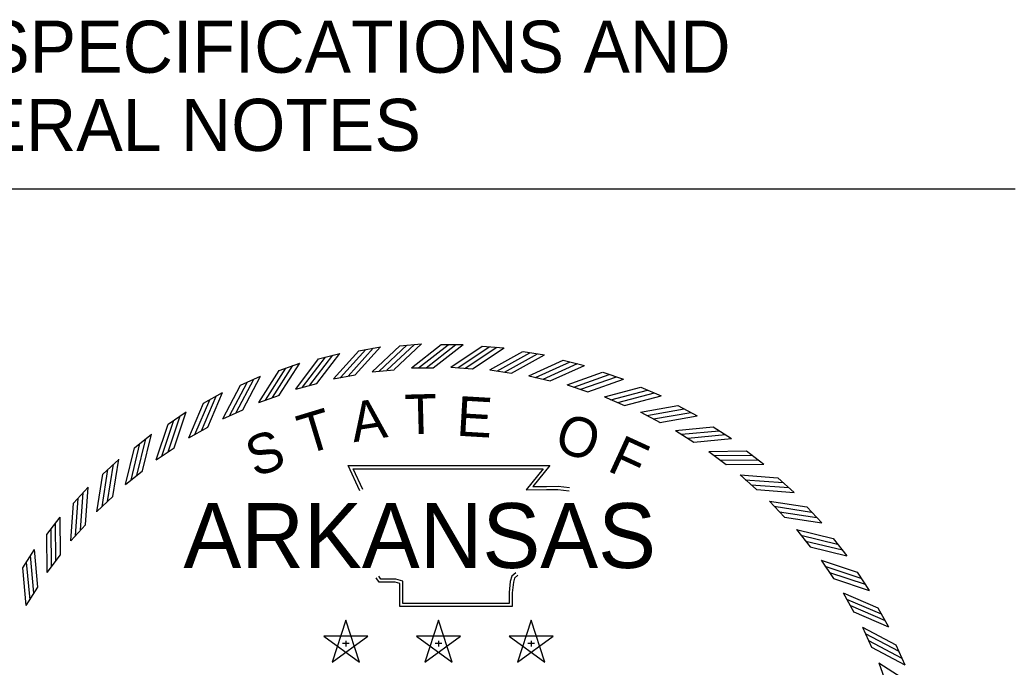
# Model space of a CAD drawing. Extents: x 1955708 to 1956002, y 566396 to 566594.
# Drawn here: x 1955978.59 to 1956002.45, y 566578.57 to 566594.1 of the extents above; entities that cross this region are included whole.
import ezdxf

# ---------------------------------------------------------------- set-up
doc = ezdxf.new("R2010")
doc.units = 0
doc.layers.add('R_Border', color=7, linetype='Continuous')
doc.layers.add('STAMP_PP', color=7, linetype='Continuous')

msp = doc.modelspace()

# ---------------------------------------------------------------- linework, layer by layer
at = {"layer": 'R_Border'}
for p, q in [((1956002.362, 566590.034), (1955939.812, 566590.034)), ((1956002.452, 566590.034), (1955959.352, 566590.034))]:
    msp.add_line(p, q, dxfattribs=at)
at = {"layer": 'STAMP_PP'}
for p, q in [((1955986.717, 566586.161), (1955987.233, 566586.252)), ((1955987.698, 566586.278), (1955988.219, 566586.326)), ((1955988.69, 566586.307), (1955989.214, 566586.307)), ((1955989.671, 566586.268), (1955990.194, 566586.229)), ((1955985.749, 566585.963), (1955986.256, 566586.096)), ((1955990.651, 566586.141), (1955991.169, 566586.059)), ((1955984.801, 566585.686), (1955985.295, 566585.861)), ((1955988.917, 566585.764), (1955989.441, 566585.726)), ((1955991.617, 566585.933), (1955992.126, 566585.809)), ((1955983.879, 566585.332), (1955984.357, 566585.547)), ((1955986.109, 566585.487), (1955986.627, 566585.579)), ((1955987.037, 566585.657), (1955987.56, 566585.705)), ((1955987.975, 566585.75), (1955988.5, 566585.75)), ((1955989.858, 566585.701), (1955990.377, 566585.619)), ((1955990.79, 566585.56), (1955991.3, 566585.436)), ((1955992.562, 566585.646), (1955993.059, 566585.481)), ((1955985.199, 566585.242), (1955985.707, 566585.375)), ((1955991.707, 566585.343), (1955992.206, 566585.177)), ((1955982.989, 566584.902), (1955983.448, 566585.156)), ((1955984.313, 566584.922), (1955984.808, 566585.097)), ((1955992.604, 566585.051), (1955993.086, 566584.845)), ((1955993.48, 566585.283), (1955993.962, 566585.077)), ((1955994.366, 566584.844), (1955994.829, 566584.599)), ((1955982.138, 566584.401), (1955982.574, 566584.692)), ((1955983.455, 566584.53), (1955983.934, 566584.745)), ((1955993.473, 566584.686), (1955993.937, 566584.44)), ((1955995.211, 566584.334), (1955995.653, 566584.052)), ((1955981.331, 566583.831), (1955981.742, 566584.157)), ((1955982.633, 566584.068), (1955983.093, 566584.323)), ((1955994.309, 566584.25), (1955994.751, 566583.967)), ((1955981.852, 566583.54), (1955982.289, 566583.832)), ((1955995.106, 566583.747), (1955995.523, 566583.428)), ((1955996.012, 566583.756), (1955996.429, 566583.438)), ((1955980.574, 566583.197), (1955980.956, 566583.555)), ((1955981.117, 566582.95), (1955981.529, 566583.276)), ((1955995.859, 566583.18), (1955996.248, 566582.828)), ((1955996.763, 566583.114), (1955997.152, 566582.763)), ((1955979.872, 566582.502), (1955980.223, 566582.891)), ((1955980.434, 566582.301), (1955980.817, 566582.66)), ((1955996.562, 566582.552), (1955996.921, 566582.169)), ((1955997.458, 566582.412), (1955997.816, 566582.03)), ((1955979.23, 566581.751), (1955979.548, 566582.168)), ((1955979.806, 566581.597), (1955980.159, 566581.987)), ((1955997.211, 566581.869), (1955997.538, 566581.457)), ((1955998.092, 566581.655), (1955998.418, 566581.244)), ((1955978.652, 566580.95), (1955978.934, 566581.392)), ((1955979.239, 566580.844), (1955979.558, 566581.262)), ((1955997.802, 566581.134), (1955998.093, 566580.697)), ((1955998.662, 566580.848), (1955998.953, 566580.412)), ((1955978.736, 566580.047), (1955979.019, 566580.49)), ((1955998.329, 566580.353), (1955998.584, 566579.893)), ((1955999.164, 566579.997), (1955999.417, 566579.539)), ((1955986.4, 566579.696), (1955986.072, 566578.69)), ((1955986.727, 566578.69), (1955986.401, 566579.697)), ((1955988.623, 566579.696), (1955988.295, 566578.69)), ((1955988.949, 566578.69), (1955988.623, 566579.697)), ((1955990.845, 566579.696), (1955990.518, 566578.69)), ((1955991.172, 566578.69), (1955990.846, 566579.697)), ((1955998.791, 566579.531), (1955999.006, 566579.052)), ((1955986.928, 566579.312), (1955985.871, 566579.313)), ((1955985.871, 566579.312), (1955986.727, 566578.689)), ((1955986.073, 566578.69), (1955986.93, 566579.311)), ((1955986.325, 566579.143), (1955986.482, 566579.143)), ((1955986.401, 566579.199), (1955986.401, 566579.066)), ((1955989.151, 566579.312), (1955988.093, 566579.313)), ((1955988.094, 566579.312), (1955988.949, 566578.689)), ((1955988.296, 566578.69), (1955989.152, 566579.311)), ((1955988.547, 566579.143), (1955988.705, 566579.143)), ((1955988.624, 566579.199), (1955988.624, 566579.066)), ((1955991.374, 566579.312), (1955990.316, 566579.313)), ((1955990.317, 566579.312), (1955991.172, 566578.689)), ((1955990.519, 566578.69), (1955991.375, 566579.311)), ((1955990.77, 566579.143), (1955990.927, 566579.143)), ((1955990.846, 566579.199), (1955990.846, 566579.066)), ((1955999.593, 566579.107), (1955999.808, 566578.63)), ((1955999.183, 566578.674), (1955999.358, 566578.178))]:
    msp.add_line(p, q, dxfattribs=at)
for points in [[(1955986.626, 566585.579), (1955987.233, 566586.252)], [(1955987.036, 566585.657), (1955987.697, 566586.277)], [(1955987.204, 566585.671), (1955987.865, 566586.291)], [(1955987.385, 566585.691), (1955988.046, 566586.312)], [(1955987.559, 566585.706), (1955988.22, 566586.326)], [(1955987.974, 566585.749), (1955988.689, 566586.307)], [(1955988.143, 566585.748), (1955988.858, 566586.305)], [(1955988.325, 566585.752), (1955989.04, 566586.309)], [(1955988.499, 566585.75), (1955989.214, 566586.308)], [(1955988.917, 566585.764), (1955989.671, 566586.267)], [(1955989.085, 566585.75), (1955989.839, 566586.254)], [(1955989.267, 566585.741), (1955990.021, 566586.244)], [(1955985.362, 566585.283), (1955985.912, 566586.004)], [(1955985.537, 566585.333), (1955986.087, 566586.054)], [(1955985.706, 566585.376), (1955986.256, 566586.097)], [(1955986.109, 566585.487), (1955986.716, 566586.16)], [(1955986.275, 566585.515), (1955986.882, 566586.188)], [(1955986.454, 566585.55), (1955987.061, 566586.224)], [(1955989.441, 566585.726), (1955990.195, 566586.23)], [(1955989.857, 566585.701), (1955990.65, 566586.14)], [(1955990.024, 566585.673), (1955990.817, 566586.113)], [(1955990.204, 566585.649), (1955990.997, 566586.088)], [(1955990.376, 566585.62), (1955991.169, 566586.06)], [(1955984.642, 566585.04), (1955985.13, 566585.805)], [(1955984.807, 566585.097), (1955985.295, 566585.861)], [(1955985.199, 566585.241), (1955985.748, 566585.962)], [(1955990.789, 566585.56), (1955991.616, 566585.933)], [(1955990.953, 566585.519), (1955991.779, 566585.891)], [(1955991.131, 566585.48), (1955991.957, 566585.852)], [(1955991.3, 566585.437), (1955992.126, 566585.809)], [(1955983.934, 566584.745), (1955984.357, 566585.547)], [(1955984.312, 566584.921), (1955984.8, 566585.685)], [(1955984.472, 566584.976), (1955984.96, 566585.74)], [(1955991.707, 566585.343), (1955992.561, 566585.646)], [(1955991.866, 566585.288), (1955992.721, 566585.591)], [(1955992.04, 566585.235), (1955992.895, 566585.538)], [(1955983.455, 566584.529), (1955983.878, 566585.331)], [(1955983.609, 566584.597), (1955984.033, 566585.399)], [(1955983.774, 566584.675), (1955984.197, 566585.477)], [(1955992.205, 566585.178), (1955993.06, 566585.481)], [(1955982.939, 566584.239), (1955983.294, 566585.073)], [(1955983.092, 566584.323), (1955983.448, 566585.157)], [(1955992.603, 566585.051), (1955993.479, 566585.283)], [(1955992.757, 566584.983), (1955993.634, 566585.215)], [(1955992.926, 566584.915), (1955993.803, 566585.147)], [(1955993.086, 566584.845), (1955993.963, 566585.077)], [(1955982.633, 566584.068), (1955982.989, 566584.902)], [(1955982.781, 566584.148), (1955983.137, 566584.982)], [(1955993.472, 566584.686), (1955994.365, 566584.844)], [(1955982.142, 566583.736), (1955982.428, 566584.597)], [(1955982.289, 566583.832), (1955982.574, 566584.692)], [(1955993.62, 566584.606), (1955994.513, 566584.764)], [(1955993.783, 566584.524), (1955994.676, 566584.682)], [(1955993.936, 566584.441), (1955994.829, 566584.599)], [(1955981.852, 566583.54), (1955982.138, 566584.4)], [(1955981.993, 566583.632), (1955982.279, 566584.492)], [(1955994.308, 566584.25), (1955995.211, 566584.334)], [(1955981.528, 566583.276), (1955981.742, 566584.157)], [(1955994.449, 566584.158), (1955995.352, 566584.242)], [(1955994.604, 566584.063), (1955995.507, 566584.147)], [(1955981.25, 566583.053), (1955981.464, 566583.934)], [(1955981.39, 566583.169), (1955981.604, 566584.05)], [(1955994.751, 566583.968), (1955995.653, 566584.052)], [(1955981.117, 566582.949), (1955981.331, 566583.83)], [(1955995.105, 566583.747), (1955996.012, 566583.756)], [(1955995.238, 566583.644), (1955996.145, 566583.653)], [(1955980.688, 566582.542), (1955980.828, 566583.437)], [(1955980.816, 566582.66), (1955980.957, 566583.556)], [(1955986.737, 566582.8), (1955986.458, 566583.405), (1955991.291, 566583.408), (1955990.887, 566582.9), (1955991.216, 566582.905), (1955991.49, 566582.908), (1955991.764, 566582.878)], [(1955995.385, 566583.536), (1955996.292, 566583.545)], [(1955995.523, 566583.429), (1955996.43, 566583.438)], [(1955980.434, 566582.3), (1955980.574, 566583.196)], [(1955980.558, 566582.414), (1955980.698, 566583.31)], [(1955986.807, 566582.832), (1955986.578, 566583.328), (1955991.132, 566583.331), (1955990.727, 566582.822), (1955991.217, 566582.828), (1955991.486, 566582.832), (1955991.756, 566582.802)], [(1955995.858, 566583.18), (1955996.762, 566583.114)], [(1955995.982, 566583.066), (1955996.886, 566583)], [(1955996.12, 566582.947), (1955997.024, 566582.881)], [(1955980.04, 566581.858), (1955980.105, 566582.763)], [(1955980.158, 566581.987), (1955980.224, 566582.891)], [(1955996.248, 566582.828), (1955997.152, 566582.763)], [(1955979.806, 566581.597), (1955979.872, 566582.501)], [(1955979.921, 566581.721), (1955979.986, 566582.625)], [(1955996.561, 566582.552), (1955997.457, 566582.412)], [(1955996.675, 566582.428), (1955997.571, 566582.288)], [(1955996.803, 566582.298), (1955997.699, 566582.158)], [(1955979.45, 566581.124), (1955979.441, 566582.031)], [(1955979.557, 566581.262), (1955979.548, 566582.168)], [(1955996.921, 566582.17), (1955997.817, 566582.03)], [(1955979.239, 566580.844), (1955979.23, 566581.75)], [(1955979.343, 566580.977), (1955979.333, 566581.883)], [(1955997.21, 566581.869), (1955998.092, 566581.655)], [(1955997.314, 566581.736), (1955998.195, 566581.522)], [(1955997.43, 566581.596), (1955998.311, 566581.382)], [(1955978.923, 566580.343), (1955978.839, 566581.246)], [(1955979.018, 566580.489), (1955978.934, 566581.392)], [(1955997.537, 566581.458), (1955998.419, 566581.244)], [(1955978.828, 566580.188), (1955978.744, 566581.091)], [(1955997.801, 566581.134), (1955998.661, 566580.849)], [(1955997.893, 566580.993), (1955998.754, 566580.707)], [(1955978.736, 566580.047), (1955978.652, 566580.949)], [(1955990.529, 566580.775), (1955990.447, 566580.708), (1955990.42, 566580.607), (1955990.392, 566580.357), (1955990.392, 566580.023), (1955987.695, 566580.023), (1955987.695, 566580.474), (1955987.695, 566580.574), (1955987.585, 566580.607), (1955987.201, 566580.607), (1955987.133, 566580.712)], [(1955990.481, 566580.834), (1955990.38, 566580.752), (1955990.344, 566580.622), (1955990.316, 566580.361), (1955990.316, 566580.099), (1955987.771, 566580.099), (1955987.771, 566580.474), (1955987.771, 566580.631), (1955987.597, 566580.684), (1955987.243, 566580.684), (1955987.197, 566580.753)], [(1955997.997, 566580.844), (1955998.858, 566580.558)], [(1955998.093, 566580.698), (1955998.953, 566580.412)], [(1955998.329, 566580.353), (1955999.163, 566579.997)], [(1955998.409, 566580.205), (1955999.243, 566579.849)], [(1955998.501, 566580.048), (1955999.335, 566579.692)], [(1955998.584, 566579.894), (1955999.418, 566579.538)], [(1955998.79, 566579.531), (1955999.592, 566579.108)], [(1955998.858, 566579.377), (1955999.66, 566578.953)], [(1955998.936, 566579.212), (1955999.738, 566578.789)], [(1955999.007, 566579.053), (1955999.808, 566578.629)], [(1955999.182, 566578.674), (1955999.947, 566578.186)]]:
    msp.add_lwpolyline(points, dxfattribs=at)

# ---------------------------------------------------------------- texts
at = {"layer": 'R_Border'}
for s, p in [('GOVERNING SPECIFICATIONS AND', (1955967.023, 566592.827)), ('GENERAL NOTES', (1955973.992, 566590.952))]:
    msp.add_text(s, height=1.25, rotation=360, dxfattribs=at).set_placement(p)
at = {"layer": 'STAMP_PP'}
for s, rotation, p in [('T', 1.4789, (1955987.821, 566584.153)), ('E', 356.672, (1955989.041, 566584.124)), ('A', 8.6788, (1955986.59, 566583.964)), ('T', 16.9015, (1955985.433, 566583.661)), ('O', 341.2218, (1955991.356, 566583.797)), ('S', 19.7726, (1955984.22, 566583.117)), ('F', 335.3628, (1955992.641, 566583.295))]:
    msp.add_text(s, height=0.953, rotation=rotation, dxfattribs=at).set_placement(p)
msp.add_text('ARKANSAS', height=1.5559, dxfattribs=at).set_placement((1955982.508, 566580.949))

doc.saveas('drawing.dxf')
